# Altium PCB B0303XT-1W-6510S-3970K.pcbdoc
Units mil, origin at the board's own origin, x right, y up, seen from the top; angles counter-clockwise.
Board outline 1024.18 x 969.92 mil, 2 copper layers (Top Layer, Bottom Layer), stack 30.709 mil thick; 8 components, 8 nets, 27 pads, 7 vias.
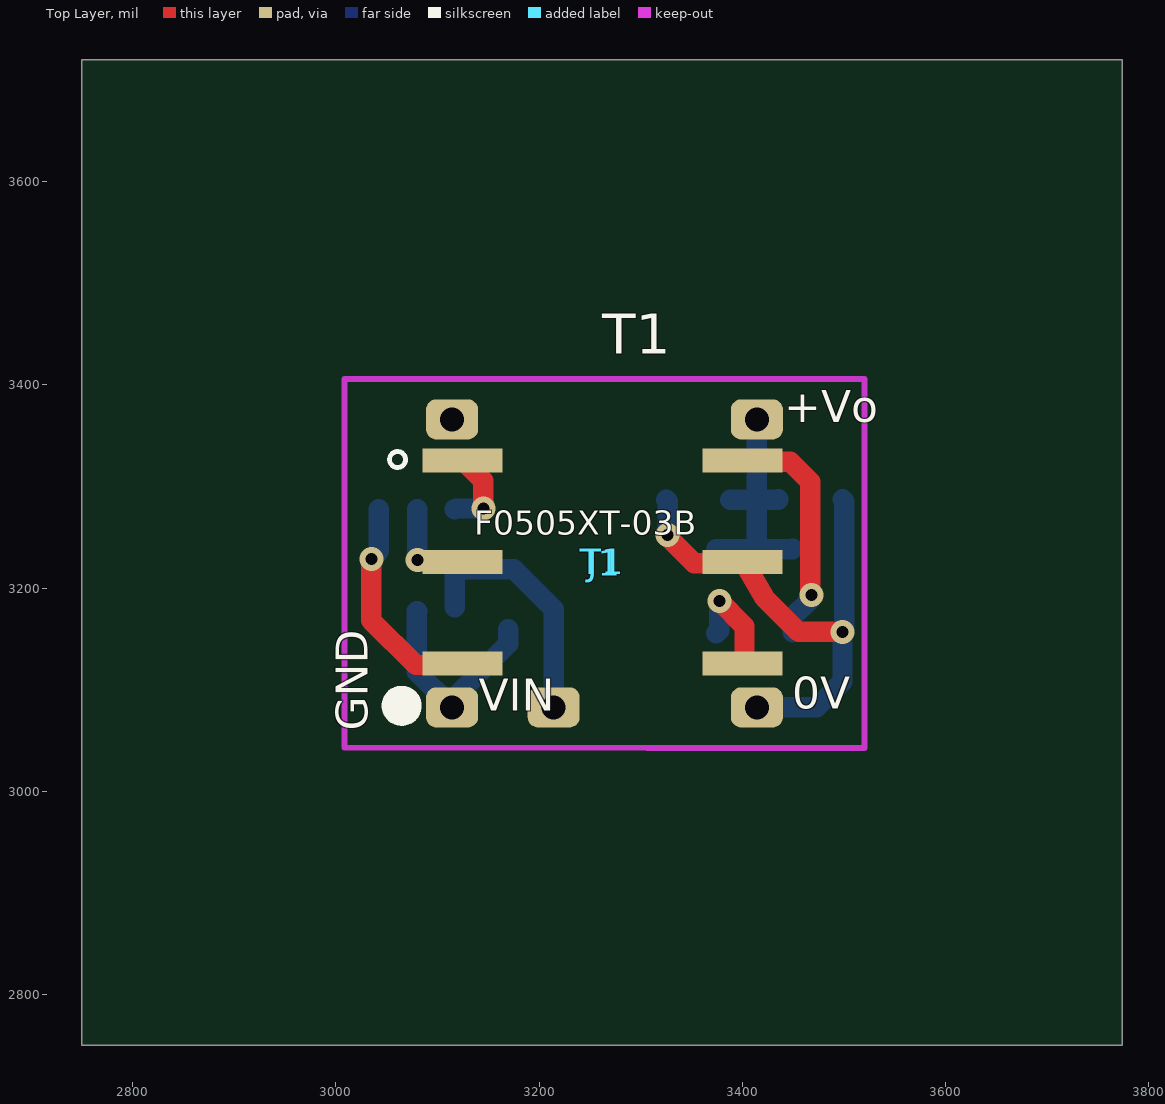
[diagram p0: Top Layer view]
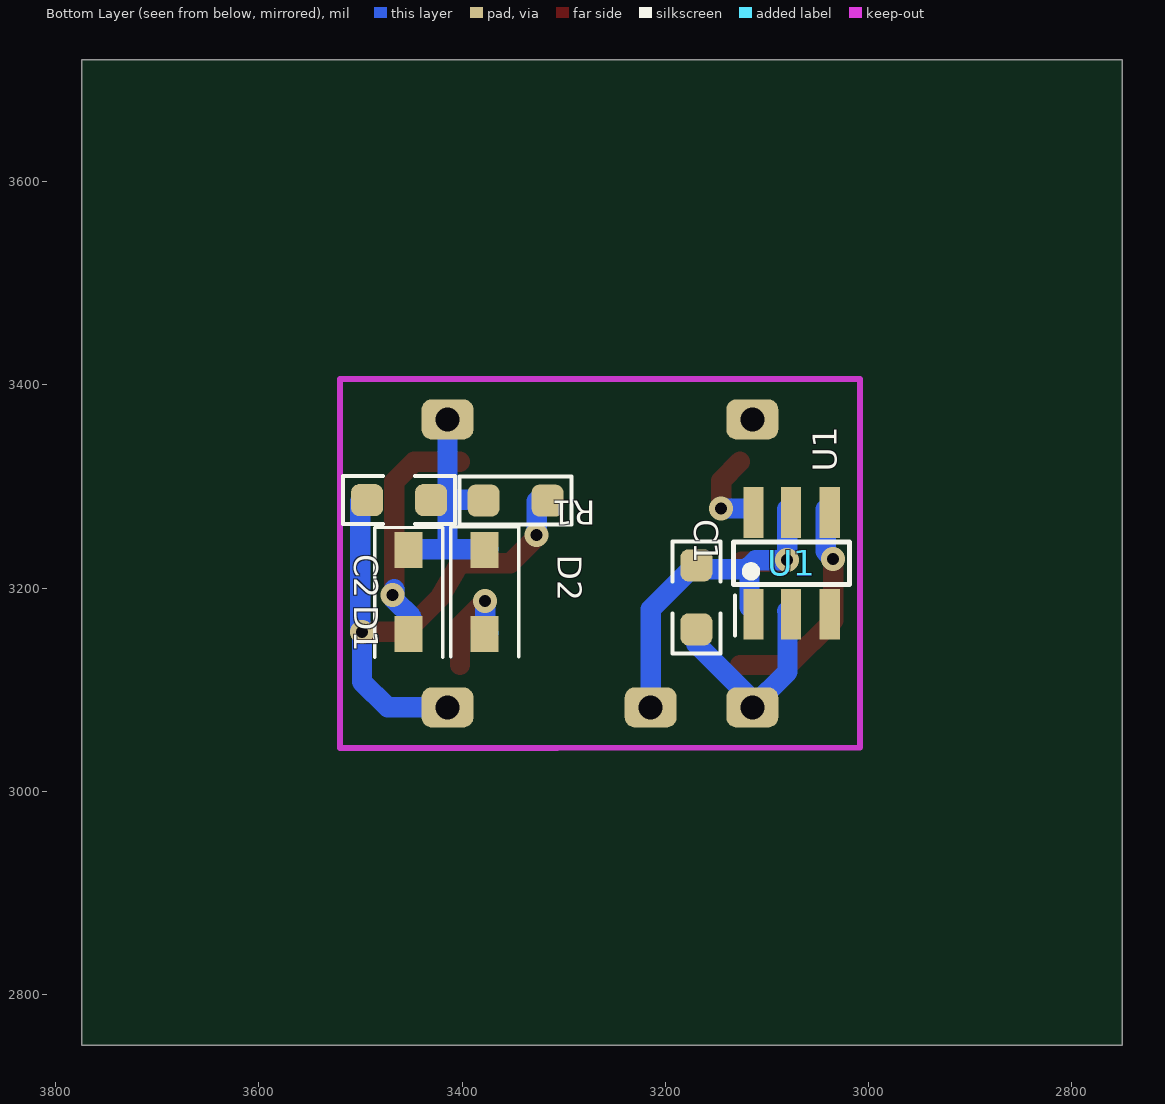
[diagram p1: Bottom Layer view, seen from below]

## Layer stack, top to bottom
Top Solder Mask Layer: solder mask 0.394, Dk 3.3
Top Layer: signal copper 1.378
Dielectric2: surface 27.953, FR4, Dk 4.5
Bottom Layer: signal copper 1.378
Bottom Solder Mask Layer: solder mask 0.394, Dk 3.3

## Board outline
3774.18,2750 2750,2750 2750,3719.92 3774.18,3719.92

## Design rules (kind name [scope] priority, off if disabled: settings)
BoardOutlineClearance copperThickness1oz [All] p0: genericclearance=10 ignorepadtopadclearanceinfootprint=FALSE except(0: Arc-SplitContinuation Track-SplitContinuation SMDPad-SplitContinuation THPad-SplitContinuation Via-SplitContinuation Fill-SplitContinuation Poly-SplitContinuation Region-SplitContinuation Text-SplitContinuation)
BoardOutlineClearance otherClearance [All] p0: genericclearance=10 ignorepadtopadclearanceinfootprint=FALSE except(0: Arc-SplitContinuation Track-SplitContinuation SMDPad-SplitContinuation THPad-SplitContinuation Via-SplitContinuation Fill-SplitContinuation Poly-SplitContinuation Region-SplitContinuation Text-SplitContinuation)
Clearance copperThickness1oz [All] p1: gap=7 ignorepadtopadclearanceinfootprint=FALSE
Clearance otherClearance [All] p1: gap=7 ignorepadtopadclearanceinfootprint=FALSE
DiffPairsRouting differentialPair [All] p1: maxuncoupledlength=10 minlimit=5 maxlimit=Infinity mostfreqgap=6 toplayer_minwidth=5 toplayer_prefwidth=100 toplayer_maxwidth=100 bottomlayer_minwidth=5 bottomlayer_prefwidth=100 bottomlayer_maxwidth=100
PasteMaskExpansion pasteMaskExpansion [All] p1: expansion=0
PlaneConnect innerPlane [All] p1: planeconnectstyle=Relief reliefexpansion=20 reliefentries=4 reliefconductorwidth=10 reliefairgap=10
PolygonConnect copperRegion [All] p1: connectstyle=Relief reliefentries=4 reliefconductorwidth=10 polygonreliefangle="90 Angle" airgapwidth=10
RoutingVias viaSize [All] p1: viastyle="Through Hole" holewidth=24 minholewidth=11.811 maxholewidth=393.7 width=24 minwidth=11.811 maxwidth=393.7
SolderMaskExpansion solderMaskExpansion [All] p1: useseparateexpansions=TRUE expansion=2 expansionbottom=2
Width copperThickness1oz [All] p1: maxlimit=100 minlimit=5 preferedwidth=10

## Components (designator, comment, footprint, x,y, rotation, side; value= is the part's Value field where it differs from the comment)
C1 "10uF" C0603 3169.45,3190.94 r90 bottom
C2 "10uF" C0603 3461.97,3286.61 r180 bottom
D1 "B5819WS" SOD-323_L1.8-W1.3-LS2.5-RD 3452.52,3196.06 r270 bottom
D2 "B5819WS" SOD-323_L1.8-W1.3-LS2.5-RD 3377.72,3196.46 r270 bottom
J1 "Connector_Generic_Conn_01x08" MYLibrary:F0505XT-8PIN 3264.33,3224.41 r0 top
R1 "4.7kΩ" R0603 3347.41,3286.22 r0 bottom
T1 "" ?#1 3262.21,3225.83 r0 top
U1 "" ?#2 3081.26,3224.41 r90 bottom

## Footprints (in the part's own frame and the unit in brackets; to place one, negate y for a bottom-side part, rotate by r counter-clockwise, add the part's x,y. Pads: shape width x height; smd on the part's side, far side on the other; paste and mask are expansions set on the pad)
C0603 [mm]
  rrect50% 0.8x0.8 smd: 1(-0.8,0) 2(0.8,0)
  silkscreen extent -1.4,-0.6 1.4,0.6
MYLibrary:F0505XT-8PIN [mm]
  rrect50% 1.3x1 hole 0.6: 1(-3.81,-3.6) 2(-1.27,-3.6) 4(3.81,-3.6) 5(3.81,3.6) 8(-3.81,3.6)
  silkscreen extent -5.32,-3.81 -4.82,-3.31
R0603 [mm]
  rrect50% 0.8x0.8 smd: 1(-0.8,0) 2(0.8,0)
  silkscreen extent -1.4,-0.6 1.4,0.6
SOD-323_L1.8-W1.3-LS2.5-RD [mm]
  rect 0.9x0.7 smd: 1(-1.05,0) 2(1.05,0)
  silkscreen extent -1.62,-0.85 1.63,0.85
?#1 [mm]
  rect 2x0.6 smd: 1(-3.5,2.54) 2(-3.5,0) 3(-3.5,-2.54) 4(3.5,-2.54) 5(3.5,0) 6(3.5,2.54)
  silkscreen extent -5.32,2.36 -4.92,2.76
?#2 [mm]
  rect 1.27x0.508 smd: 1(-1.27,0.813) 2(-1.27,-0.127) 3(-1.27,-1.092) 4(1.27,-1.092) 5(1.27,-0.127) 6(1.27,0.813)
  silkscreen extent -1.8,-1.59 0.53,1.31

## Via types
v1: diameter 23.62, hole 11.81, Top Layer to Bottom Layer, 7 vias

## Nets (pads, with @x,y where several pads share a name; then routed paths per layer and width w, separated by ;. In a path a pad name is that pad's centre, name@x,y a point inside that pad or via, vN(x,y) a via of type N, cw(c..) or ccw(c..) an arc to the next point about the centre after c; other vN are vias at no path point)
0V: C2.1 J1.4 R1.1 T1.5 | length 528.9
  Top Layer w20: v1(3326.54,3252.36) 3326.54,3250.39 3352.52,3224.41 3402.13,3224.41 3421.82,3190.55 3455.28,3157.09 v1(3498.59,3157.09)
  Bottom Layer w20: R1.1@3324.96,3287.01 3326.54,3285.43 v1(3326.54,3252.36) ; J1.4 3473.39,3082.68 3498.59,3107.87 v1(3498.59,3157.09) 3500.16,3158.66 3500.16,3285.83 C2.1@3498.59,3287.4
$1N17: T1.1 U1.6 | length 82.6
  Top Layer w20: T1.1@3126.54,3324.41 3145.04,3305.91 v1(3145.04,3278.35)
  Bottom Layer w20: U1.6@3116.7,3277.94 3117.08,3277.56 3117.87,3278.35 v1(3145.04,3278.35)
$1N18: T1.3 U1.4 | length 222.3
  Top Layer w20: v1(3034.81,3228.8) 3034.81,3168.11 3078.51,3124.41 T1.3@3126.54,3124.41
  Bottom Layer w20: v1(3034.81,3228.8) 3042.08,3236.07 U1.4@3042.08,3277.56
$1N19: D2.2 T1.4 | length 106.5
  Top Layer w20: v1(3377.33,3187.4) 3402.13,3162.6 T1.4@3402.13,3124.41
  Bottom Layer w20: D2.2@3374.18,3155.51 3377.33,3158.66 v1(3377.33,3187.4)
$1N20: D1.2 T1.6 | length 234.3
  Top Layer w20: T1.6@3402.13,3324.41 3447.01,3324.41 3466.7,3304.72 3466.7,3194.88 v1(3468.27,3193.31)
  Bottom Layer w20: D1.2@3449.77,3156.3 3449.77,3171.65 3466.7,3188.58 v1@3466.7,3198.82
+V0: C2.2 D1.1 D2.1 J1.5 R1.2 | length 252
  Bottom Layer w20: D2.1@3374.18,3238.19 3413.55,3238.19 ; R1.2@3387.96,3287.01 3414.33,3287.01 ; J1.5 3414.33,3287.01 ; C2.2@3435.59,3287.4 3435.2,3287.01 3414.33,3287.01 ; D1.1@3449.77,3238.98 3448.98,3238.19 3413.55,3238.19 ; 3413.55,3238.19 3414.33,3238.98 3414.33,3287.01
GND1: C1.1 J1.1 U1.2 | length 208.6
  Bottom Layer w20: U1.2@3080.08,3177.56 3079.69,3177.17 3079.69,3117.72 J1.1@3114.33,3083.07 ; J1.1 J1.1@3114.33,3083.07 ; C1.1 3169.45,3145.28 3114.33,3090.16 J1.1@3114.33,3083.07
VIN: C1.2 J1.2 T1.2 U1.1 U1.5 | length 396.7
  Top Layer w20: v1(3080.08,3227.56) 3081.66,3225.98 3124.96,3225.98 T1.2@3126.54,3224.41
  Bottom Layer w20: U1.5@3080.08,3277.56 v1(3080.08,3227.56) 3111.18,3227.56 3120.23,3218.5 ; U1.1@3117.08,3181.1 3117.08,3215.35 3120.23,3218.5 ; J1.2@3204.89,3082.68 J1.2 3214.33,3179.13 3174.96,3218.5 3120.23,3218.5
pads on no net: J1.8 U1.3

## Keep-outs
Board Outline Layer:
  lines w5.91: 3520.24,3042.91 3306.07,3042.91 3008.43,3043.11 3008.43,3405.71 3520.24,3405.71 3520.24,3043.11

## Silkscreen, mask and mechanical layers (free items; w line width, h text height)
Top Silkscreen Layer:
  text "+Vo" at 3441.11,3363.54 h31.5
  text "F0505XT-03B" at 3135.99,3252.36 h23.62
  text "0V" at 3449.33,3081.54 h31.5
  text "VIN" at 3140.71,3079.57 h31.5
  text "GND" at 3031.5,3059.45 h31.5 r90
